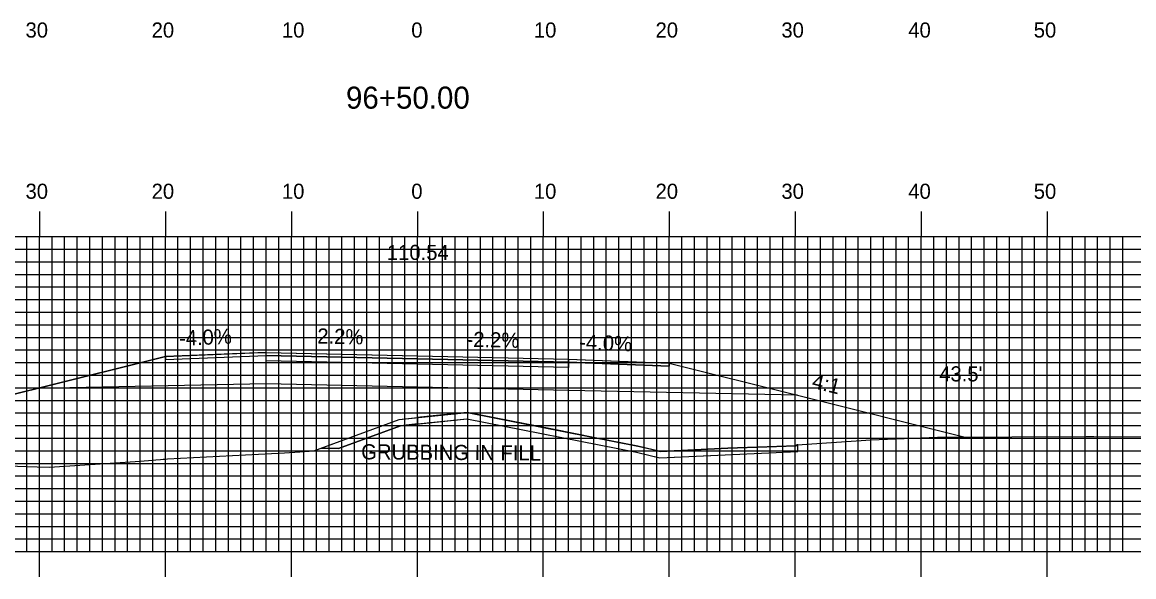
# Model space of a CAD drawing. Extents: x 1765726 to 1766069, y 442591 to 442811.
# Drawn here: x 1765860.5 to 1765948.8, y 442701.7 to 442745.7 of the extents above; entities that cross this region are included whole.
import ezdxf

# ---------------------------------------------------------------- set-up
doc = ezdxf.new("R2010")
doc.units = 0
for name, color, linetype in [('ANNOTATION', 7, 'Continuous'), ('D_Roadway_Centerline', 7, 'Continuous'), ('D_Roadway_Centerline_Text', 7, 'Continuous'), ('D_Roadway_Edge_Shoulder', 7, 'Continuous'), ('D_Roadway_Edge_TW', 7, 'Continuous'), ('D_Roadway_Pavement', 7, 'Continuous'), ('D_Roadway_SlopeLines', 7, 'Continuous'), ('D_Roadway_SubGrade', 7, 'Continuous'), ('D_Text_Standard', 7, 'Continuous'), ('GRUBBING IN FILL', 7, 'Continuous'), ('H_V ANNOTATION', 7, 'Continuous'), ('MAJOR', 7, 'Continuous'), ('MINOR', 7, 'Continuous'), ('S_Roadway_Centerline', 7, 'Continuous')]:
    doc.layers.add(name, color=color, linetype=linetype)

msp = doc.modelspace()

# ---------------------------------------------------------------- linework, layer by layer
at = {"layer": 'D_Roadway_Centerline'}
msp.add_lwpolyline([(1765841.804, 442711.629), (1765845.904, 442712.654), (1765859.884, 442716.15), (1765860.723, 442716.36), (1765861.71, 442716.606), (1765865.412, 442717.532), (1765871.883, 442719.15), (1765871.884, 442719.15), (1765878.825, 442719.428), (1765879.884, 442719.47), (1765883.447, 442719.392), (1765891.884, 442719.206), (1765903.884, 442718.942), (1765903.885, 442718.942), (1765909.956, 442718.699), (1765911.884, 442718.622), (1765922.058, 442716.078), (1765935.366, 442712.751)], dxfattribs=at)
at = {"layer": 'D_Roadway_Edge_Shoulder'}
for points in [[(1765879.884, 442719.47), (1765871.884, 442719.15), (1765871.884, 442718.9), (1765879.884, 442719.22)], [(1765903.884, 442718.942), (1765911.884, 442718.622), (1765911.884, 442718.372), (1765903.884, 442718.692)]]:
    msp.add_lwpolyline(points, close=True, dxfattribs=at)
at = {"layer": 'D_Roadway_Edge_TW'}
msp.add_lwpolyline([(1765879.884, 442719.22), (1765879.884, 442719.47), (1765891.884, 442719.206), (1765903.884, 442718.942), (1765903.884, 442718.692), (1765891.884, 442718.956)], close=True, dxfattribs=at)
at = {"layer": 'D_Roadway_Pavement'}
msp.add_lwpolyline([(1765879.884, 442718.803), (1765879.884, 442719.22), (1765891.884, 442718.956), (1765903.884, 442718.692), (1765903.884, 442718.275), (1765891.884, 442718.539)], close=True, dxfattribs=at)
at = {"layer": 'D_Roadway_SlopeLines'}
for points in [[(1765871.884, 442719.15), (1765861.71, 442716.606), (1765859.884, 442716.15), (1765841.804, 442711.629)], [(1765911.884, 442718.622), (1765922.058, 442716.078), (1765935.366, 442712.751)]]:
    msp.add_lwpolyline(points, dxfattribs=at)
at = {"layer": 'D_Roadway_SubGrade'}
msp.add_lwpolyline([(1765879.884, 442716.97), (1765861.71, 442716.606), (1765871.884, 442719.15), (1765871.884, 442718.9), (1765879.884, 442719.22), (1765891.884, 442718.956), (1765903.884, 442718.692), (1765911.884, 442718.372), (1765911.884, 442718.622), (1765922.058, 442716.078), (1765903.884, 442716.442), (1765891.884, 442716.706)], close=True, dxfattribs=at)
at = {"layer": 'GRUBBING IN FILL'}
msp.add_line((1765922.088, 442711.615), (1765922.088, 442712.131), dxfattribs=at)
msp.add_line((1765922.088, 442711.615), (1765922.088, 442712.131), dxfattribs=at)
for points in [[(1765891.884, 442713.792), (1765890.556, 442713.65), (1765885.622, 442711.844), (1765884.25, 442711.874), (1765887.057, 442712.902), (1765890.442, 442714.141), (1765891.884, 442714.295)], [(1765891.884, 442713.792), (1765890.556, 442713.65), (1765885.622, 442711.844), (1765884.25, 442711.874), (1765887.057, 442712.902), (1765890.442, 442714.141), (1765891.884, 442714.295)], [(1765922.088, 442712.131), (1765922.031, 442712.127), (1765921.933, 442712.056), (1765920.429, 442712.001), (1765916.541, 442711.859), (1765912.821, 442711.687), (1765911.17, 442711.61), (1765909.388, 442712.035), (1765906.01, 442712.702), (1765902.607, 442713.375), (1765895.825, 442714.714), (1765893.133, 442714.428), (1765891.884, 442714.295), (1765891.884, 442713.792), (1765893.179, 442713.93), (1765895.803, 442714.209), (1765909.283, 442711.546), (1765911.121, 442711.107), (1765922.088, 442711.615)], [(1765922.088, 442712.131), (1765922.031, 442712.127), (1765921.933, 442712.056), (1765920.429, 442712.001), (1765916.541, 442711.859), (1765912.821, 442711.687), (1765911.17, 442711.61), (1765909.388, 442712.035), (1765906.01, 442712.702), (1765902.607, 442713.375), (1765895.825, 442714.714), (1765893.133, 442714.428), (1765891.884, 442714.295), (1765891.884, 442713.792), (1765893.179, 442713.93), (1765895.803, 442714.209), (1765909.283, 442711.546), (1765911.121, 442711.107), (1765922.088, 442711.615)]]:
    msp.add_lwpolyline(points, close=True, dxfattribs=at)
for points in [[(1765885.622, 442711.844), (1765890.556, 442713.65), (1765895.803, 442714.209), (1765909.283, 442711.546), (1765910.353, 442711.297), (1765911.121, 442711.107), (1765912.845, 442711.188), (1765922.088, 442711.615)], [(1765885.622, 442711.844), (1765890.556, 442713.65), (1765895.803, 442714.209), (1765909.283, 442711.546), (1765910.353, 442711.297), (1765911.121, 442711.107), (1765912.845, 442711.188), (1765922.088, 442711.615)], [(1765884.25, 442711.874), (1765885.622, 442711.844)], [(1765884.25, 442711.874), (1765885.622, 442711.844)]]:
    msp.add_lwpolyline(points, dxfattribs=at)
at = {"layer": 'MAJOR'}
for p, q in [((1765861.884, 442730.669), (1765861.884, 442728.665)), ((1765871.884, 442730.669), (1765871.884, 442728.665)), ((1765881.884, 442730.669), (1765881.884, 442728.665)), ((1765891.884, 442730.669), (1765891.884, 442728.665)), ((1765901.884, 442730.669), (1765901.884, 442728.665)), ((1765911.884, 442730.669), (1765911.884, 442728.665)), ((1765921.884, 442730.669), (1765921.884, 442728.665)), ((1765931.884, 442730.669), (1765931.884, 442728.665)), ((1765941.884, 442730.669), (1765941.884, 442728.665)), ((1765751.884, 442728.665), (1766031.884, 442728.665)), ((1765751.884, 442728.665), (1766031.884, 442728.665)), ((1765861.884, 442703.665), (1765861.884, 442728.665)), ((1765871.884, 442703.665), (1765871.884, 442728.665)), ((1765881.884, 442703.665), (1765881.884, 442728.665)), ((1765891.884, 442703.665), (1765891.884, 442728.665)), ((1765901.884, 442703.665), (1765901.884, 442728.665)), ((1765911.884, 442703.665), (1765911.884, 442728.665)), ((1765921.884, 442703.665), (1765921.884, 442728.665)), ((1765931.884, 442703.665), (1765931.884, 442728.665)), ((1765941.884, 442703.665), (1765941.884, 442728.665)), ((1765751.884, 442723.665), (1766031.884, 442723.665)), ((1765751.884, 442718.665), (1766031.884, 442718.665)), ((1765751.884, 442713.665), (1766031.884, 442713.665)), ((1765751.884, 442708.665), (1766031.884, 442708.665)), ((1765751.884, 442703.665), (1766031.884, 442703.665)), ((1765751.884, 442703.665), (1766031.884, 442703.665)), ((1765861.884, 442701.661), (1765861.884, 442703.665)), ((1765871.884, 442701.661), (1765871.884, 442703.665)), ((1765881.884, 442701.661), (1765881.884, 442703.665)), ((1765891.884, 442701.661), (1765891.884, 442703.665)), ((1765901.884, 442701.661), (1765901.884, 442703.665)), ((1765911.884, 442701.661), (1765911.884, 442703.665)), ((1765921.884, 442701.661), (1765921.884, 442703.665)), ((1765931.884, 442701.661), (1765931.884, 442703.665)), ((1765941.884, 442701.661), (1765941.884, 442703.665))]:
    msp.add_line(p, q, dxfattribs=at)
at = {"layer": 'MINOR'}
for p, q in [((1765860.884, 442703.665), (1765860.884, 442728.665)), ((1765862.884, 442703.665), (1765862.884, 442728.665)), ((1765863.884, 442703.665), (1765863.884, 442728.665)), ((1765864.884, 442703.665), (1765864.884, 442728.665)), ((1765865.884, 442703.665), (1765865.884, 442728.665)), ((1765866.884, 442703.665), (1765866.884, 442728.665)), ((1765867.884, 442703.665), (1765867.884, 442728.665)), ((1765868.884, 442703.665), (1765868.884, 442728.665)), ((1765869.884, 442703.665), (1765869.884, 442728.665)), ((1765870.884, 442703.665), (1765870.884, 442728.665)), ((1765872.884, 442703.665), (1765872.884, 442728.665)), ((1765873.884, 442703.665), (1765873.884, 442728.665)), ((1765874.884, 442703.665), (1765874.884, 442728.665)), ((1765875.884, 442703.665), (1765875.884, 442728.665)), ((1765876.884, 442703.665), (1765876.884, 442728.665)), ((1765877.884, 442703.665), (1765877.884, 442728.665)), ((1765878.884, 442703.665), (1765878.884, 442728.665)), ((1765879.884, 442703.665), (1765879.884, 442728.665)), ((1765880.884, 442703.665), (1765880.884, 442728.665)), ((1765882.884, 442703.665), (1765882.884, 442728.665)), ((1765883.884, 442703.665), (1765883.884, 442728.665)), ((1765884.884, 442703.665), (1765884.884, 442728.665)), ((1765885.884, 442703.665), (1765885.884, 442728.665)), ((1765886.884, 442703.665), (1765886.884, 442728.665)), ((1765887.884, 442703.665), (1765887.884, 442728.665)), ((1765888.884, 442703.665), (1765888.884, 442728.665)), ((1765889.884, 442703.665), (1765889.884, 442728.665)), ((1765890.884, 442703.665), (1765890.884, 442728.665)), ((1765892.884, 442703.665), (1765892.884, 442728.665)), ((1765893.884, 442703.665), (1765893.884, 442728.665)), ((1765894.884, 442703.665), (1765894.884, 442728.665)), ((1765895.884, 442703.665), (1765895.884, 442728.665)), ((1765896.884, 442703.665), (1765896.884, 442728.665)), ((1765897.884, 442703.665), (1765897.884, 442728.665)), ((1765898.884, 442703.665), (1765898.884, 442728.665)), ((1765899.884, 442703.665), (1765899.884, 442728.665)), ((1765900.884, 442703.665), (1765900.884, 442728.665)), ((1765902.884, 442703.665), (1765902.884, 442728.665)), ((1765903.884, 442703.665), (1765903.884, 442728.665)), ((1765904.884, 442703.665), (1765904.884, 442728.665)), ((1765905.884, 442703.665), (1765905.884, 442728.665)), ((1765906.884, 442703.665), (1765906.884, 442728.665)), ((1765907.884, 442703.665), (1765907.884, 442728.665)), ((1765908.884, 442703.665), (1765908.884, 442728.665)), ((1765909.884, 442703.665), (1765909.884, 442728.665)), ((1765910.884, 442703.665), (1765910.884, 442728.665)), ((1765912.884, 442703.665), (1765912.884, 442728.665)), ((1765913.884, 442703.665), (1765913.884, 442728.665)), ((1765914.884, 442703.665), (1765914.884, 442728.665)), ((1765915.884, 442703.665), (1765915.884, 442728.665)), ((1765916.884, 442703.665), (1765916.884, 442728.665)), ((1765917.884, 442703.665), (1765917.884, 442728.665)), ((1765918.884, 442703.665), (1765918.884, 442728.665)), ((1765919.884, 442703.665), (1765919.884, 442728.665)), ((1765920.884, 442703.665), (1765920.884, 442728.665)), ((1765922.884, 442703.665), (1765922.884, 442728.665)), ((1765923.884, 442703.665), (1765923.884, 442728.665)), ((1765924.884, 442703.665), (1765924.884, 442728.665)), ((1765925.884, 442703.665), (1765925.884, 442728.665)), ((1765926.884, 442703.665), (1765926.884, 442728.665)), ((1765927.884, 442703.665), (1765927.884, 442728.665)), ((1765928.884, 442703.665), (1765928.884, 442728.665)), ((1765929.884, 442703.665), (1765929.884, 442728.665)), ((1765930.884, 442703.665), (1765930.884, 442728.665)), ((1765932.884, 442703.665), (1765932.884, 442728.665)), ((1765933.884, 442703.665), (1765933.884, 442728.665)), ((1765934.884, 442703.665), (1765934.884, 442728.665)), ((1765935.884, 442703.665), (1765935.884, 442728.665)), ((1765936.884, 442703.665), (1765936.884, 442728.665)), ((1765937.884, 442703.665), (1765937.884, 442728.665)), ((1765938.884, 442703.665), (1765938.884, 442728.665)), ((1765939.884, 442703.665), (1765939.884, 442728.665)), ((1765940.884, 442703.665), (1765940.884, 442728.665)), ((1765942.884, 442703.665), (1765942.884, 442728.665)), ((1765943.884, 442703.665), (1765943.884, 442728.665)), ((1765944.884, 442703.665), (1765944.884, 442728.665)), ((1765945.884, 442703.665), (1765945.884, 442728.665)), ((1765946.884, 442703.665), (1765946.884, 442728.665)), ((1765947.884, 442703.665), (1765947.884, 442728.665)), ((1765751.884, 442727.665), (1766031.884, 442727.665)), ((1765751.884, 442726.665), (1766031.884, 442726.665)), ((1765751.884, 442725.665), (1766031.884, 442725.665)), ((1765751.884, 442724.665), (1766031.884, 442724.665)), ((1765751.884, 442722.665), (1766031.884, 442722.665)), ((1765751.884, 442721.665), (1766031.884, 442721.665)), ((1765751.884, 442720.665), (1766031.884, 442720.665)), ((1765751.884, 442719.665), (1766031.884, 442719.665)), ((1765751.884, 442717.665), (1766031.884, 442717.665)), ((1765751.884, 442716.665), (1766031.884, 442716.665)), ((1765751.884, 442715.665), (1766031.884, 442715.665)), ((1765751.884, 442714.665), (1766031.884, 442714.665)), ((1765751.884, 442712.665), (1766031.884, 442712.665)), ((1765751.884, 442711.665), (1766031.884, 442711.665)), ((1765751.884, 442710.665), (1766031.884, 442710.665)), ((1765751.884, 442709.665), (1766031.884, 442709.665)), ((1765751.884, 442707.665), (1766031.884, 442707.665)), ((1765751.884, 442706.665), (1766031.884, 442706.665)), ((1765751.884, 442705.665), (1766031.884, 442705.665)), ((1765751.884, 442704.665), (1766031.884, 442704.665))]:
    msp.add_line(p, q, dxfattribs=at)
at = {"layer": 'S_Roadway_Centerline'}
msp.add_lwpolyline([(1765859.342, 442710.459), (1765861.697, 442710.382), (1765862.695, 442710.349), (1765867.107, 442710.657), (1765869.489, 442710.824), (1765870.545, 442710.899), (1765871.129, 442710.941), (1765871.487, 442710.968), (1765871.704, 442710.985), (1765871.886, 442711), (1765872.038, 442711.013), (1765881.347, 442711.502), (1765882.562, 442711.585), (1765883.673, 442711.663), (1765890.442, 442714.141), (1765895.825, 442714.714), (1765909.388, 442712.035), (1765910.47, 442711.783), (1765911.17, 442711.61), (1765912.821, 442711.687), (1765916.541, 442711.859), (1765921.933, 442712.056), (1765922.031, 442712.127), (1765927.885, 442712.542), (1765933.166, 442712.742), (1765944.977, 442712.79), (1765945.573, 442712.795), (1765957.666, 442712.722)], dxfattribs=at)

# ---------------------------------------------------------------- texts
at = {"layer": 'ANNOTATION'}
for s, rotation, p in [('-4.0%', 2.29072, (1765872.987, 442719.996)), ('2.2%', 358.73973, (1765883.93, 442720.182)), ('-2.2%', 358.73973, (1765895.776, 442719.921)), ('-4.0%', 357.70925, (1765904.712, 442719.711)), ('4:1', 345.96247, (1765923.131, 442716.672))]:
    msp.add_text(s, height=1.2, rotation=rotation, dxfattribs=at).set_placement(p)
at = {"layer": 'D_Roadway_Centerline'}
for s, p in [('C', (1765891.879, 442719.206)), ('L', (1765891.884, 442719.199))]:
    msp.add_text(s, height=0.0146, dxfattribs=at).set_placement(p)
at = {"layer": 'D_Roadway_Centerline_Text'}
msp.add_text('110.54', height=1.2, dxfattribs=at).set_placement((1765889.466, 442726.811))
at = {"layer": 'D_Text_Standard'}
msp.add_text("43.5'", height=1.2, dxfattribs=at).set_placement((1765933.307, 442717.167))
at = {"layer": 'GRUBBING IN FILL'}
msp.add_text('GRUBBING IN FILL', height=1.2, rotation=359.60519, dxfattribs=at).set_placement((1765887.421, 442710.985))
at = {"layer": 'H_V ANNOTATION'}
for s, height, p in [('30', 1.2, (1765860.781, 442744.465)), ('20', 1.2, (1765870.792, 442744.465)), ('10', 1.2, (1765881.135, 442744.465)), ('0', 1.2, (1765891.402, 442744.465)), ('10', 1.2, (1765901.135, 442744.465)), ('20', 1.2, (1765910.792, 442744.465)), ('30', 1.2, (1765920.781, 442744.465)), ('40', 1.2, (1765930.856, 442744.465)), ('50', 1.2, (1765940.813, 442744.465)), ('96+50.00', 1.75, (1765886.219, 442738.821)), ('30', 1.2, (1765860.781, 442731.665)), ('20', 1.2, (1765870.792, 442731.665)), ('10', 1.2, (1765881.135, 442731.665)), ('0', 1.2, (1765891.402, 442731.665)), ('10', 1.2, (1765901.135, 442731.665)), ('20', 1.2, (1765910.792, 442731.665)), ('30', 1.2, (1765920.781, 442731.665)), ('40', 1.2, (1765930.856, 442731.665)), ('50', 1.2, (1765940.813, 442731.665))]:
    msp.add_text(s, height=height, dxfattribs=at).set_placement(p)

doc.saveas('drawing.dxf')
